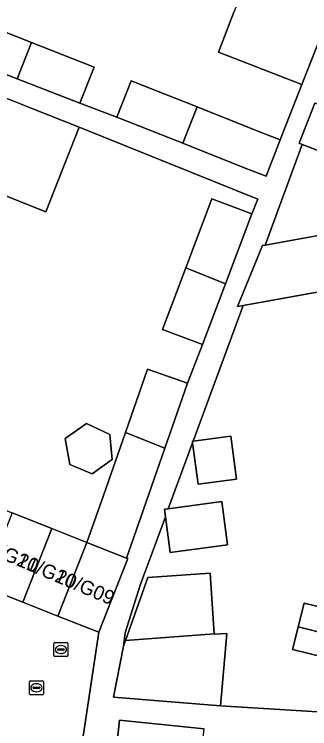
# Model space of a CAD drawing. Extents: x 161248 to 161848, y 384871 to 385383.
# Drawn here: x 161619.1 to 161640.1, y 385046.9 to 385097.6 of the extents above; entities that cross this region are included whole.
import ezdxf

# ---------------------------------------------------------------- set-up
doc = ezdxf.new("R2010")
doc.units = 0
for name, color, linetype in [('IMGEO_Erf', 7, 'Continuous'), ('IMGEO_Kolk', 7, 'Continuous'), ('IMGEO_Pand', 7, 'Continuous'), ('IMGEO_Pand_nummerreeks', 7, 'Continuous'), ('IMGEO_Rijbaan_lokaal_open', 7, 'Continuous'), ('IMGEO_Rioolput', 7, 'Continuous'), ('IMGEO_Voetpad_open', 7, 'Continuous')]:
    doc.layers.add(name, color=color, linetype=linetype)

msp = doc.modelspace()

# ---------------------------------------------------------------- linework, layer by layer
at = {"layer": 'IMGEO_Erf'}
for points in [[(161616.549, 385114.582), (161609.588, 385096.835), (161614.636, 385094.855), (161615.65, 385097.431), (161620.326, 385095.589), (161624.77, 385093.838), (161623.756, 385091.263), (161626.377, 385090.292), (161627.391, 385092.868), (161632.074, 385091.023), (161636.5, 385089.247), (161637.964, 385088.681), (161639.51, 385092.589), (161633.583, 385094.893), (161634.689, 385097.731)], [(161641.209, 385087.692), (161639.537, 385088.353), (161636.912, 385081.209), (161640.815, 385081.913)], [(161641.516, 385078.03), (161635.334, 385076.913), (161631.801, 385067.298), (161634.458, 385067.655), (161634.869, 385064.595), (161632.151, 385064.23), (161631.756, 385067.174), (161630.035, 385062.492), (161633.823, 385063.001), (161634.235, 385059.933), (161630.169, 385059.387), (161629.828, 385061.927), (161628.048, 385057.083), (161626.986, 385053.694), (161626.864, 385052.737), (161627.006, 385053.142), (161628.582, 385057.621), (161632.994, 385057.929), (161633.294, 385053.613), (161633.296, 385053.589), (161634.195, 385053.653), (161633.732, 385048.516), (161642.146, 385047.983)], [(161641.073, 385051.953), (161638.85, 385052.515), (161639.226, 385054.001), (161639.253, 385054.107), (161639.678, 385055.785), (161641.734, 385055.297)]]:
    msp.add_lwpolyline(points, dxfattribs=at)
for points in [[(161626.99, 385067.908), (161628.56, 385072.404), (161631.405, 385071.41), (161632.453, 385074.14), (161629.619, 385075.21), (161631.269, 385079.579), (161633.123, 385084.488), (161635.956, 385083.418), (161636.375, 385084.451), (161623.722, 385089.58), (161621.352, 385083.563), (161618.055, 385084.861), (161615.77, 385079.061), (161613.474, 385073.232), (161613.278, 385072.734), (161616.802, 385071.346), (161613.971, 385064.16), (161616.133, 385063.308), (161618.953, 385062.198), (161621.771, 385061.087), (161624.266, 385060.105), (161625.428, 385063.434)], [(161624.639, 385064.968), (161623.06, 385065.638), (161622.733, 385067.469), (161624.224, 385068.545), (161625.881, 385067.762), (161626.04, 385066.235), (161626.065, 385065.998), (161625.908, 385065.884)]]:
    msp.add_lwpolyline(points, close=True, dxfattribs=at)
at = {"layer": 'IMGEO_Kolk'}
for p, q in [((161620.184, 385049.368), (161620.184, 385050.22)), ((161620.259, 385050.294), (161621.111, 385050.294)), ((161621.185, 385050.22), (161621.185, 385049.368)), ((161620.443, 385049.788), (161620.443, 385049.8)), ((161620.881, 385049.751), (161620.483, 385049.751)), ((161620.486, 385049.837), (161620.884, 385049.837)), ((161620.672, 385050.074), (161620.697, 385050.074)), ((161620.927, 385049.8), (161620.927, 385049.788)), ((161621.111, 385049.294), (161620.259, 385049.294)), ((161620.695, 385049.514), (161620.67, 385049.514))]:
    msp.add_line(p, q, dxfattribs=at)
for points in [[(161620.184, 385049.368), (161620.184, 385050.22)], [(161620.259, 385050.294), (161621.111, 385050.294)], [(161621.185, 385050.22), (161621.185, 385049.368)], [(161621.111, 385049.294), (161620.259, 385049.294)]]:
    msp.add_lwpolyline(points, dxfattribs=at)
for centre, radius, start, end in [((161620.261, 385050.218), 0.0765, 91.552, 178.448), ((161620.261, 385050.218), 0.0765, 91.552, 178.448), ((161621.109, 385050.218), 0.0765, 1.552, 88.448), ((161621.109, 385050.218), 0.0765, 1.552, 88.448), ((161620.483, 385049.797), 0.0403, 85.8775, 175.7526), ((161620.48, 385049.787), 0.0366, 178.938, 274.7102), ((161620.884, 385049.794), 0.043, 264.8664, 352.4533), ((161620.888, 385049.799), 0.0386, 1.7309, 96.639), ((161620.261, 385049.37), 0.0765, 181.552, 268.448), ((161620.261, 385049.37), 0.0765, 181.552, 268.448), ((161621.109, 385049.37), 0.0765, 271.552, 358.448), ((161621.109, 385049.37), 0.0765, 271.552, 358.448)]:
    msp.add_arc(centre, radius, start, end, dxfattribs=at)
for centre, major_axis, ratio, start_param, end_param in [((161620.671, 385049.794), (-0.387, 0.002), 0.722429, 4.712389, 7.853982), ((161620.696, 385049.794), (-0.39, 0.002), 0.717154, 1.570796, 4.712389)]:
    msp.add_ellipse(centre, major_axis=major_axis, ratio=ratio, start_param=start_param, end_param=end_param, dxfattribs=at)
at = {"layer": 'IMGEO_Pand'}
for points in [[(161643.642, 385103.129), (161637.698, 385105.451), (161634.689, 385097.731), (161633.583, 385094.893), (161639.51, 385092.589), (161640.622, 385095.425)], [(161620.326, 385095.589), (161615.65, 385097.431), (161614.636, 385094.855), (161619.318, 385093.011)], [(161619.318, 385093.011), (161623.756, 385091.263), (161624.77, 385093.838), (161620.326, 385095.589)], [(161618.055, 385084.861), (161621.352, 385083.563), (161623.722, 385089.58), (161620.425, 385090.878), (161617.33, 385092.097), (161612.677, 385093.93), (161610.322, 385087.952)], [(161627.391, 385092.868), (161626.377, 385090.292), (161631.069, 385088.444), (161632.074, 385091.023)], [(161642.331, 385090.531), (161640.43, 385091.283), (161639.307, 385088.444), (161639.537, 385088.353), (161641.209, 385087.692)], [(161632.074, 385091.023), (161631.069, 385088.444), (161635.485, 385086.669), (161636.964, 385086.097), (161637.964, 385088.681), (161636.5, 385089.247)], [(161631.269, 385079.579), (161634.082, 385078.455), (161635.956, 385083.418), (161633.123, 385084.488)], [(161636.912, 385081.209), (161636.704, 385081.171), (161634.937, 385076.841), (161635.334, 385076.913), (161641.516, 385078.03), (161640.815, 385081.913)], [(161634.082, 385078.455), (161631.269, 385079.579), (161629.619, 385075.21), (161632.453, 385074.14)], [(161631.405, 385071.41), (161628.56, 385072.404), (161626.99, 385067.908), (161629.797, 385066.802)], [(161624.639, 385064.968), (161625.908, 385065.884), (161626.065, 385065.998), (161626.04, 385066.235), (161625.881, 385067.762), (161624.224, 385068.545), (161622.733, 385067.469), (161623.06, 385065.638)], [(161629.797, 385066.802), (161626.99, 385067.908), (161625.428, 385063.434), (161624.266, 385060.105), (161627.072, 385058.999), (161628.274, 385062.44)], [(161631.801, 385067.298), (161631.74, 385067.29), (161631.756, 385067.174), (161632.151, 385064.23), (161634.869, 385064.595), (161634.458, 385067.655)], [(161630.035, 385062.492), (161629.757, 385062.455), (161629.828, 385061.927), (161630.169, 385059.387), (161634.235, 385059.933), (161633.823, 385063.001)], [(161621.771, 385061.087), (161618.953, 385062.198), (161616.892, 385056.967), (161619.711, 385055.856)], [(161624.266, 385060.105), (161621.771, 385061.087), (161619.711, 385055.856), (161622.205, 385054.874)], [(161627.072, 385058.999), (161624.266, 385060.105), (161622.205, 385054.874), (161625.106, 385053.731), (161627.167, 385058.962)], [(161633.294, 385053.613), (161632.994, 385057.929), (161628.582, 385057.621), (161627.006, 385053.142)], [(161653.254, 385055.951), (161644.741, 385058.102), (161644.032, 385055.295), (161641.855, 385055.811), (161641.734, 385055.297), (161639.678, 385055.785), (161639.253, 385054.107), (161651.975, 385050.892)], [(161651.975, 385050.892), (161639.253, 385054.107), (161639.226, 385054.001), (161638.85, 385052.515), (161641.073, 385051.953), (161640.961, 385051.508), (161642.912, 385051.015), (161642.146, 385047.983), (161645.847, 385047.047), (161650.694, 385045.822)], [(161627.006, 385053.142), (161626.864, 385052.737), (161626.146, 385049.118), (161633.732, 385048.516), (161634.195, 385053.653), (161633.296, 385053.589), (161633.294, 385053.613)], [(161626.039, 385042.415), (161631.969, 385041.839), (161632.575, 385046.872), (161626.568, 385047.499)]]:
    msp.add_lwpolyline(points, close=True, dxfattribs=at)
at = {"layer": 'IMGEO_Rijbaan_lokaal_open'}
msp.add_lwpolyline([(161601.032, 385060.606), (161596.479, 385072.714), (161592.706, 385071.279), (161596.272, 385062.029), (161595.047, 385046.848), (161598.222, 385046.534), (161598.264, 385046.957), (161601.308, 385046.655), (161604.353, 385046.353), (161607.397, 385046.051), (161610.442, 385045.75), (161613.486, 385045.448), (161616.53, 385045.146), (161619.575, 385044.844), (161622.619, 385044.542), (161623.721, 385044.472), (161625.106, 385053.731), (161622.205, 385054.874), (161619.711, 385055.856), (161616.892, 385056.967)], dxfattribs=at)
at = {"layer": 'IMGEO_Rioolput'}
for p, q in [((161621.919, 385052.08), (161621.919, 385052.932)), ((161621.994, 385053.006), (161622.846, 385053.006)), ((161622.407, 385052.786), (161622.432, 385052.786)), ((161622.92, 385052.932), (161622.92, 385052.08)), ((161622.178, 385052.5), (161622.178, 385052.512)), ((161622.616, 385052.463), (161622.218, 385052.463)), ((161622.221, 385052.549), (161622.619, 385052.549)), ((161622.43, 385052.226), (161622.405, 385052.226)), ((161622.662, 385052.512), (161622.662, 385052.5)), ((161622.846, 385052.006), (161621.994, 385052.006))]:
    msp.add_line(p, q, dxfattribs=at)
for points in [[(161621.919, 385052.08), (161621.919, 385052.932)], [(161621.994, 385053.006), (161622.846, 385053.006)], [(161622.92, 385052.932), (161622.92, 385052.08)], [(161622.846, 385052.006), (161621.994, 385052.006)]]:
    msp.add_lwpolyline(points, dxfattribs=at)
for centre, radius, start, end in [((161621.996, 385052.93), 0.0765, 91.552, 178.448), ((161621.996, 385052.93), 0.0765, 91.552, 178.448), ((161622.844, 385052.93), 0.0765, 1.552, 88.448), ((161622.844, 385052.93), 0.0765, 1.552, 88.448), ((161622.218, 385052.509), 0.0403, 85.8775, 175.7526), ((161622.215, 385052.499), 0.0366, 178.938, 274.7102), ((161622.619, 385052.506), 0.043, 264.8664, 352.4533), ((161622.623, 385052.511), 0.0386, 1.7309, 96.639), ((161621.996, 385052.082), 0.0765, 181.552, 268.448), ((161621.996, 385052.082), 0.0765, 181.552, 268.448), ((161622.844, 385052.082), 0.0765, 271.552, 358.448), ((161622.844, 385052.082), 0.0765, 271.552, 358.448)]:
    msp.add_arc(centre, radius, start, end, dxfattribs=at)
for centre, major_axis, ratio, start_param, end_param in [((161622.406, 385052.506), (-0.387, 0.002), 0.722429, 4.712389, 7.853982), ((161622.431, 385052.506), (-0.39, 0.002), 0.717154, 1.570796, 4.712389)]:
    msp.add_ellipse(centre, major_axis=major_axis, ratio=ratio, start_param=start_param, end_param=end_param, dxfattribs=at)
at = {"layer": 'IMGEO_Voetpad_open'}
for points in [[(161640.622, 385095.425), (161639.51, 385092.589), (161637.964, 385088.681), (161636.964, 385086.097), (161635.485, 385086.669), (161631.069, 385088.444), (161626.377, 385090.292), (161623.756, 385091.263), (161619.318, 385093.011), (161614.636, 385094.855)], [(161617.33, 385092.097), (161620.425, 385090.878), (161623.722, 385089.58), (161636.375, 385084.451), (161635.956, 385083.418), (161634.082, 385078.455), (161632.453, 385074.14), (161631.405, 385071.41), (161629.797, 385066.802), (161628.274, 385062.44), (161627.072, 385058.999), (161627.167, 385058.962), (161625.106, 385053.731), (161623.721, 385044.472)], [(161642.146, 385047.983), (161633.732, 385048.516), (161626.146, 385049.118), (161626.864, 385052.737), (161626.986, 385053.694), (161628.048, 385057.083), (161629.828, 385061.927), (161629.757, 385062.455), (161630.035, 385062.492), (161631.756, 385067.174), (161631.74, 385067.29), (161631.801, 385067.298), (161635.334, 385076.913), (161634.937, 385076.841), (161636.704, 385081.171), (161636.912, 385081.209), (161639.537, 385088.353), (161639.307, 385088.444), (161640.43, 385091.283)], [(161626.039, 385042.415), (161626.568, 385047.499), (161632.575, 385046.872)]]:
    msp.add_lwpolyline(points, dxfattribs=at)

# ---------------------------------------------------------------- texts
at = {"layer": 'IMGEO_Pand_nummerreeks'}
for s, p in [('20/G11', (161616.526, 385059.645)), ('20/G10', (161619.214, 385058.502)), ('20/G09', (161621.911, 385057.356))]:
    msp.add_text(s, height=1, rotation=336.9671, dxfattribs=at).set_placement(p)

doc.saveas('drawing.dxf')
